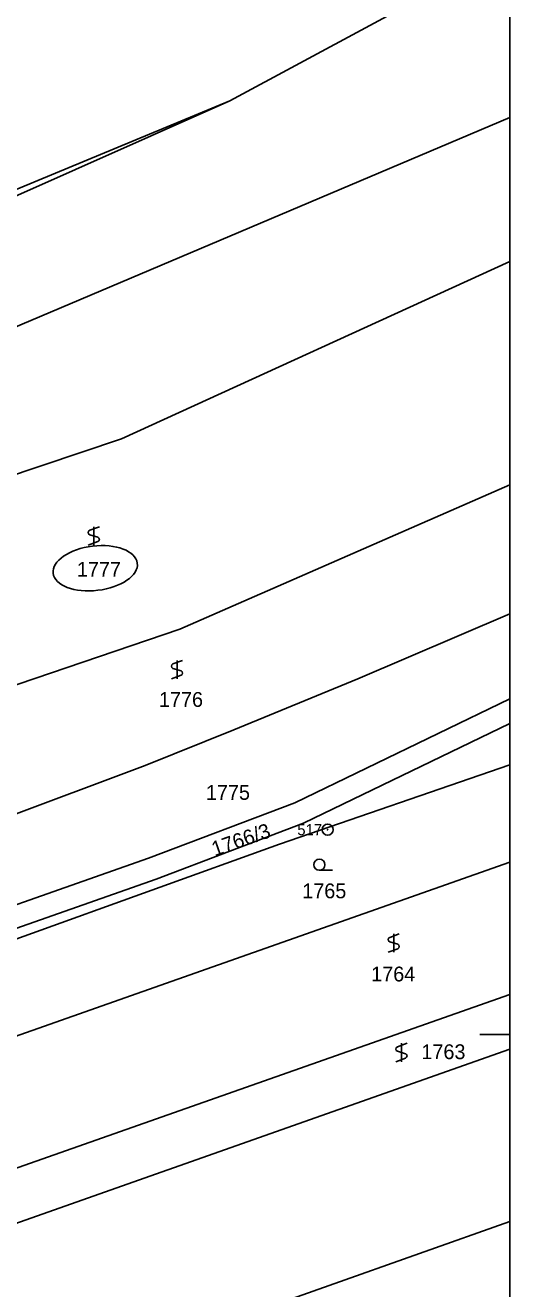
# Model space of a CAD drawing. Extents: x -601739 to -601442, y -1201912 to -1200862.
# Drawn here: x -601507.3 to -601441.8, y -1201316.7 to -1201146 of the extents above; entities that cross this region are included whole.
import ezdxf

# ---------------------------------------------------------------- set-up
doc = ezdxf.new("R2010")
doc.units = 0
for name, color, linetype in [('Hranice parcel', 7, 'Continuous'), ('Parcelní čísla', 7, 'Continuous'), ('u_dotčené parcely', 7, 'Continuous'), ('Vnitřní kresba', 7, 'Continuous'), ('x_rám', 7, 'Continuous'), ('Značky bodu BP', 7, 'Continuous'), ('Značky kultur', 7, 'Continuous')]:
    doc.layers.add(name, color=color, linetype=linetype)

msp = doc.modelspace()

# ---------------------------------------------------------------- linework, layer by layer
at = {"layer": 'Hranice parcel'}
for p, q in [((-601441.84, -1201259.06), (-601546.8, -1201296.02)), ((-601441.84, -1201284.33), (-601531.62, -1201316.01)), ((-601441.84, -1201307.6), (-601513.53, -1201332.97))]:
    msp.add_line(p, q, dxfattribs=at)
for points in [[(-601441.84, -1201135.79), (-601479.66, -1201156.2), (-601529.7, -1201176.99), (-601592.77, -1201199.55), (-601607.91, -1201202.49), (-601612.99, -1201203.33)], [(-601441.84, -1201158.45), (-601525.44, -1201193.92), (-601604.85, -1201222.33)], [(-601441.84, -1201177.92), (-601494.28, -1201201.89), (-601596.75, -1201236.33)], [(-601441.84, -1201208.07), (-601486.38, -1201227.6), (-601575.76, -1201257.99)], [(-601441.84, -1201225.51), (-601462.37, -1201234.27), (-601479.08, -1201241.2), (-601491.06, -1201246.01), (-601510.67, -1201253.32), (-601523.83, -1201257.65), (-601565.18, -1201270.36)], [(-601560.05, -1201276.34), (-601549.23, -1201278.7), (-601525.2, -1201270.68), (-601490.61, -1201258.52), (-601470.84, -1201251.03), (-601441.84, -1201236.98)], [(-601441.84, -1201240.31), (-601469.67, -1201253.79), (-601489.59, -1201261.34), (-601524.21, -1201273.51), (-601548.32, -1201281.56), (-601552.5, -1201285.17)], [(-601441.84, -1201245.89), (-601472.91, -1201256.64), (-601524.69, -1201275.26), (-601552.5, -1201285.17)], [(-601441.84, -1201276.92), (-601537.44, -1201310.56)]]:
    msp.add_lwpolyline(points, dxfattribs=at)
at = {"layer": 'u_dotčené parcely'}
msp.add_ellipse((-601497.82, -1201219.35), major_axis=(-5.69, -0.68), ratio=0.524694, dxfattribs=at)
at = {"layer": 'Vnitřní kresba'}
msp.add_line((-601529.86, -1201178.56), (-601479.66, -1201156.2), dxfattribs=at)
at = {"layer": 'x_rám'}
msp.add_line((-601441.84, -1201282.35), (-601445.88, -1201282.35), dxfattribs=at)
msp.add_lwpolyline([(-601441.84, -1200862.35), (-601441.84, -1201912.35), (-601738.84, -1201912.35), (-601738.84, -1200862.35)], close=True, dxfattribs=at)
at = {"layer": 'Značky bodu BP'}
for radius in [0.75, 0.03]:
    msp.add_circle((-601466.43, -1201254.67), radius, dxfattribs=at)
at = {"layer": 'Značky kultur'}
for p, q in [((-601497.26, -1201213.75), (-601498.56, -1201214.23)), ((-601498.01, -1201213.75), (-601498.01, -1201216.25)), ((-601498.76, -1201216.25), (-601497.46, -1201215.76)), ((-601498.56, -1201214.83), (-601497.46, -1201215.16)), ((-601486.02, -1201231.8), (-601487.32, -1201232.28)), ((-601487.32, -1201232.88), (-601486.22, -1201233.21)), ((-601486.77, -1201231.8), (-601486.77, -1201234.3)), ((-601487.52, -1201234.3), (-601486.22, -1201233.81)), ((-601467.54, -1201260.16), (-601465.79, -1201260.16)), ((-601456.75, -1201268.74), (-601458.05, -1201269.22)), ((-601457.5, -1201268.74), (-601457.5, -1201271.24)), ((-601458.25, -1201271.24), (-601456.95, -1201270.75)), ((-601458.05, -1201269.82), (-601456.95, -1201270.15)), ((-601455.71, -1201283.52), (-601457.01, -1201284)), ((-601456.46, -1201283.52), (-601456.46, -1201286.02)), ((-601457.21, -1201286.02), (-601455.91, -1201285.53)), ((-601457.01, -1201284.6), (-601455.91, -1201284.93))]:
    msp.add_line(p, q, dxfattribs=at)
msp.add_circle((-601467.54, -1201259.41), 0.75, dxfattribs=at)
for centre, start, end in [((-601498.43, -1201214.53), 113.579, 246.421), ((-601497.59, -1201215.46), 293.574, 66.426), ((-601487.19, -1201232.58), 113.579, 246.421), ((-601486.35, -1201233.51), 293.574, 66.426), ((-601457.92, -1201269.52), 113.579, 246.421), ((-601457.08, -1201270.45), 293.574, 66.426), ((-601456.88, -1201284.3), 113.579, 246.421), ((-601456.04, -1201285.23), 293.574, 66.426)]:
    msp.add_arc(centre, 0.329, start, end, dxfattribs=at)

# ---------------------------------------------------------------- texts
at = {"layer": 'Parcelní čísla'}
for s, p in [('1777', (-601500.29, -1201220.5)), ('1776', (-601489.21, -1201238.08)), ('1775', (-601482.87, -1201250.64)), ('1765', (-601469.86, -1201263.94)), ('1764', (-601460.55, -1201275.17)), ('1763', (-601453.77, -1201285.67))]:
    msp.add_text(s, height=2, dxfattribs=at).set_placement(p)
msp.add_text('1766/3', height=2, rotation=19, dxfattribs=at).set_placement((-601481.69, -1201258.3))
at = {"layer": 'Značky bodu BP'}
msp.add_text('517', height=1.5, dxfattribs=at).set_placement((-601470.53, -1201255.42))

doc.saveas('drawing.dxf')
